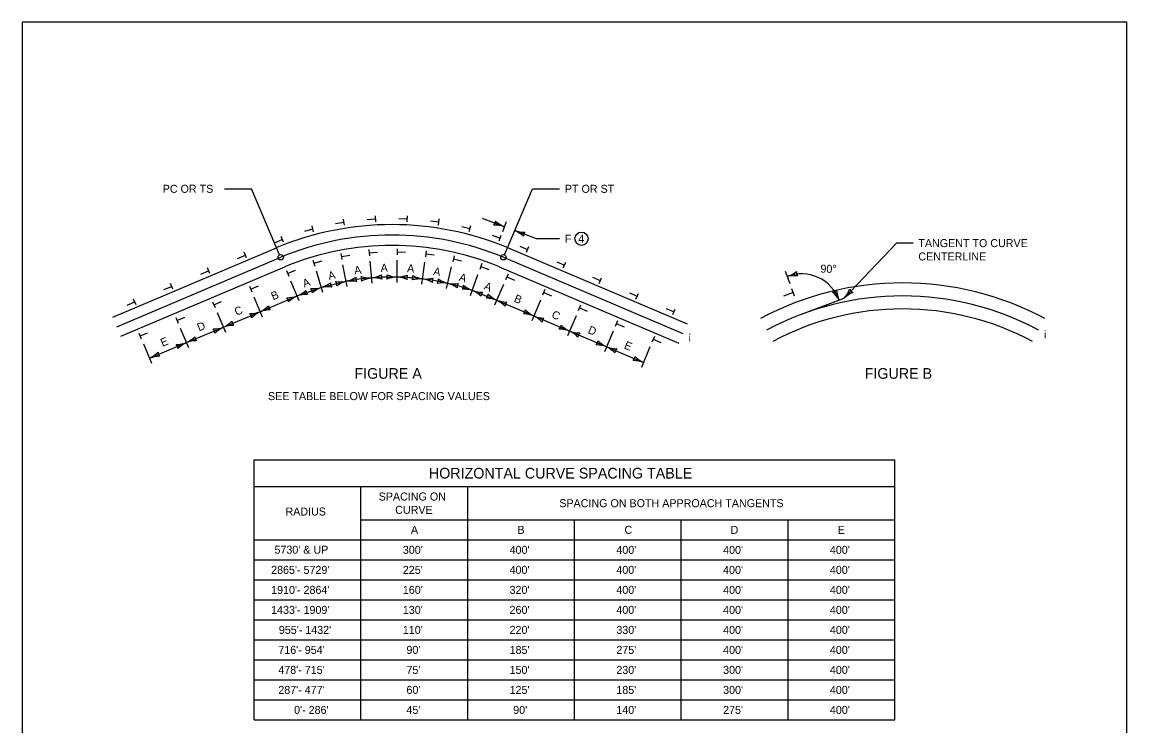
# Model space of a CAD drawing. Extents: x 49991.4 to 50021, y 49987.6 to 50011.4.
# Drawn here: x 50000.34 to 50008.61, y 50005.99 to 50011.26 of the extents above; entities that cross this region are included whole.
import ezdxf

# ---------------------------------------------------------------- set-up
doc = ezdxf.new("R2010")
doc.units = 0
for name, color, linetype in [('Level 1', 7, 'Continuous'), ('Level 2', 7, 'Continuous'), ('Level 3', 7, 'Continuous'), ('Level 5', 7, 'Continuous')]:
    doc.layers.add(name, color=color, linetype=linetype)

msp = doc.modelspace()

# ---------------------------------------------------------------- linework, layer by layer
at = {"layer": 'Level 1'}
for p, q in [((50002.9853, 50009.7645), (50002.983, 50009.8105)), ((50003.2208, 50009.765), (50003.2233, 50009.811)), ((50002.5205, 50009.6907), (50002.5088, 50009.7352)), ((50002.6849, 50009.7517), (50002.7473, 50009.7626)), ((50002.7509, 50009.7397), (50002.7438, 50009.7852)), ((50002.9209, 50009.7832), (50002.9841, 50009.7875)), ((50003.1587, 50009.7903), (50003.222, 50009.788)), ((50003.3957, 50009.7726), (50003.4585, 50009.7638)), ((50003.455, 50009.7412), (50003.4621, 50009.7866)), ((50003.6302, 50009.7306), (50003.6918, 50009.7156)), ((50003.6858, 50009.6932), (50003.6977, 50009.7377)), ((50002.2943, 50009.6118), (50002.2764, 50009.6542)), ((50002.4536, 50009.6957), (50002.5147, 50009.713)), ((50003.8588, 50009.6645), (50003.9184, 50009.643)), ((50003.9102, 50009.6216), (50003.9267, 50009.6645)), ((50001.0157, 50009.0503), (50002.243, 50009.5712)), ((50002.9344, 50009.5567), (50002.9382, 50009.5108)), ((50003.1466, 50009.5635), (50003.1457, 50009.5175)), ((50003.3634, 50009.548), (50003.3576, 50009.5023)), ((50003.9719, 50009.5714), (50005.3185, 50008.9999)), ((50004.115, 50009.5367), (50004.1329, 50009.579)), ((50002.0181, 50009.4946), (50002.0001, 50009.5369)), ((50002.5154, 50009.4773), (50002.5289, 50009.4334)), ((50002.7237, 50009.528), (50002.7324, 50009.4828)), ((50003.5731, 50009.5109), (50003.5626, 50009.4661)), ((50001.0767, 50008.9065), (50002.304, 50009.4274)), ((50001.7419, 50009.3773), (50001.7239, 50009.4197)), ((50002.3157, 50009.3993), (50002.3337, 50009.3569)), ((50003.7798, 50009.4517), (50003.7646, 50009.4083)), ((50003.9114, 50009.4274), (50005.2575, 50008.8561)), ((50004.3912, 50009.4194), (50004.4092, 50009.4618)), ((50001.4656, 50009.2601), (50001.4476, 50009.3024)), ((50003.9769, 50009.3737), (50003.9589, 50009.3313)), ((50004.6593, 50009.3035), (50004.6772, 50009.3458)), ((50006.9294, 50009.307), (50006.9294, 50009.307)), ((50002.0394, 50009.282), (50002.0574, 50009.2397)), ((50004.2531, 50009.2564), (50004.2352, 50009.2141)), ((50004.9355, 50009.1862), (50004.9535, 50009.2286)), ((50006.1148, 50009.2345), (50006.0406, 50009.2067)), ((50006.1248, 50009.2079), (50006.1046, 50009.2619)), ((50001.1893, 50009.1429), (50001.1713, 50009.1852)), ((50001.7632, 50009.1648), (50001.7812, 50009.1224)), ((50004.5212, 50009.1405), (50004.5032, 50009.0981)), ((50006.0497, 50009.1824), (50006.0497, 50009.1824)), ((50006.0497, 50009.1824), (50006.0497, 50009.1824)), ((50005.2118, 50009.069), (50005.2297, 50009.1113)), ((50001.487, 50009.0475), (50001.5049, 50009.0052)), ((50004.7974, 50009.0232), (50004.7795, 50008.9809)), ((50001.2107, 50008.9303), (50001.2286, 50008.888)), ((50005.0737, 50008.906), (50005.0557, 50008.8636))]:
    msp.add_line(p, q, dxfattribs=at)
msp.add_lwpolyline([(50008.6146, 50011.2628), (50000.3356, 50011.2628), (50000.3356, 50000.0624), (50008.6146, 50000.0624)], close=True, dxfattribs=at)
for points in [[(50002.2271, 50009.6083), (50002.2855, 50009.6331)], [(50004.0657, 50009.5826), (50004.1241, 50009.5578)], [(50001.9508, 50009.4911), (50002.0092, 50009.5159)], [(50002.5224, 50009.4553), (50002.5834, 50009.4725)], [(50002.7283, 50009.5053), (50002.7908, 50009.5163)], [(50002.9365, 50009.5336), (50002.9998, 50009.5382)], [(50003.1464, 50009.5405), (50003.2098, 50009.5384)], [(50003.3607, 50009.5251), (50003.4235, 50009.5164)], [(50003.568, 50009.4884), (50003.6293, 50009.4734)], [(50004.342, 50009.4653), (50004.4004, 50009.4405)], [(50001.6745, 50009.3738), (50001.7329, 50009.3986)], [(50002.3249, 50009.3781), (50002.3833, 50009.4029)], [(50003.7724, 50009.43), (50003.8321, 50009.4085)], [(50003.9679, 50009.3524), (50004.0263, 50009.3276)], [(50004.61, 50009.3494), (50004.6684, 50009.3246)], [(50001.3982, 50009.2565), (50001.4566, 50009.2813)], [(50002.0486, 50009.2609), (50002.107, 50009.2857)], [(50004.2442, 50009.2351), (50004.3026, 50009.2103)], [(50004.8863, 50009.2321), (50004.9447, 50009.2073)], [(50001.1219, 50009.1393), (50001.1803, 50009.1641)], [(50001.7723, 50009.1436), (50001.8307, 50009.1684)], [(50004.5122, 50009.1192), (50004.5706, 50009.0944)], [(50005.1626, 50009.1149), (50005.221, 50009.0901)], [(50001.496, 50009.0263), (50001.5544, 50009.0511)], [(50004.7885, 50009.0019), (50004.8469, 50008.9771)], [(50001.2197, 50008.9091), (50001.2781, 50008.9339)], [(50005.0648, 50008.8847), (50005.1232, 50008.8599)]]:
    msp.add_lwpolyline(points, dxfattribs=at)
for centre in [(50002.2735, 50009.4993), (50003.9419, 50009.4993)]:
    msp.add_circle(centre, 0.02, dxfattribs=at)
for centre, radius, start, end in [((50003.1077, 50007.4941), 2.2499, 67.41183, 112.58817), ((50003.1077, 50007.4941), 2.0937, 67.41183, 112.58817), ((50006.934, 50007.0492), 2.2578, 61.85387, 118.14614), ((50006.934, 50007.0492), 2.0625, 61.85387, 118.14614)]:
    msp.add_arc(centre, radius, start, end, dxfattribs=at)
at = {"layer": 'Level 2'}
for p, q in [((50002.0751, 50007.9803), (50006.8751, 50007.9803)), ((50002.0751, 50006.0303), (50002.0751, 50007.9803)), ((50006.8751, 50006.0303), (50006.8751, 50007.9803)), ((50002.0751, 50007.7803), (50006.8751, 50007.7803)), ((50002.8751, 50006.0303), (50002.8751, 50007.7803)), ((50003.6751, 50006.0303), (50003.6751, 50007.7803)), ((50002.8751, 50007.5303), (50006.8751, 50007.5303)), ((50004.4751, 50006.0303), (50004.4751, 50007.5303)), ((50005.2751, 50006.0303), (50005.2751, 50007.5303)), ((50006.0751, 50006.0303), (50006.0751, 50007.5303)), ((50002.0751, 50007.3803), (50006.8751, 50007.3803)), ((50002.0751, 50007.2303), (50006.8751, 50007.2303)), ((50002.0751, 50007.0803), (50006.8751, 50007.0803)), ((50002.0751, 50006.9303), (50006.8751, 50006.9303)), ((50002.0751, 50006.7803), (50006.8751, 50006.7803)), ((50002.0751, 50006.6303), (50006.8751, 50006.6303)), ((50002.0751, 50006.4803), (50006.8751, 50006.4803)), ((50002.0751, 50006.3303), (50006.8751, 50006.3303)), ((50002.0751, 50006.1803), (50006.8751, 50006.1803)), ((50002.0751, 50006.0303), (50006.8751, 50006.0303))]:
    msp.add_line(p, q, dxfattribs=at)
msp.add_circle((50004.5276, 50009.6383), 0.05, dxfattribs=at)
at = {"layer": 'Level 3'}
for p, q in [((50001.8522, 50010.0127), (50002.0556, 50010.0127)), ((50002.2657, 50009.5177), (50002.0556, 50010.0127)), ((50003.9497, 50009.5177), (50004.1598, 50010.0127)), ((50004.1598, 50010.0127), (50004.3631, 50010.0127)), ((50003.9488, 50009.7286), (50003.7865, 50009.7896)), ((50003.9629, 50009.7661), (50003.9348, 50009.6912)), ((50004.1891, 50009.6383), (50004.0268, 50009.6993)), ((50004.3631, 50009.6383), (50004.1891, 50009.6383)), ((50006.8868, 50009.6055), (50006.4969, 50009.1923)), ((50006.8843, 50009.6045), (50006.8843, 50009.6045)), ((50007.0118, 50009.6055), (50006.8868, 50009.6055)), ((50002.9578, 50009.3048), (50002.9431, 50009.4711)), ((50003.1453, 50009.3106), (50003.1456, 50009.4775)), ((50002.5893, 50009.2354), (50002.5406, 50009.3951)), ((50002.7718, 50009.2796), (50002.74, 50009.4435)), ((50003.3323, 50009.297), (50003.3527, 50009.4626)), ((50003.5168, 50009.2643), (50003.5537, 50009.4271)), ((50002.412, 50009.1731), (50002.3494, 50009.3201)), ((50002.5776, 50009.2737), (50002.7642, 50009.3189)), ((50003.697, 50009.2127), (50003.7515, 50009.3705)), ((50002.3963, 50009.2099), (50002.5776, 50009.2737)), ((50003.71, 50009.2506), (50003.8916, 50009.1777)), ((50003.9429, 50009.2946), (50003.876, 50009.1409)), ((50002.0727, 50009.2027), (50002.1344, 50009.0539)), ((50002.1188, 50009.0908), (50002.3963, 50009.2099)), ((50003.8916, 50009.1777), (50004.1698, 50009.0595)), ((50004.2196, 50009.1773), (50004.1542, 50009.0227)), ((50001.7968, 50009.0856), (50001.8595, 50008.9374)), ((50001.8439, 50008.9742), (50002.1188, 50009.0908)), ((50002.1176, 50009.0934), (50002.1176, 50009.0934)), ((50002.1185, 50009.0914), (50002.1185, 50009.0914)), ((50004.1698, 50009.0595), (50004.9921, 50008.7106)), ((50004.4874, 50009.0613), (50004.4221, 50008.909)), ((50001.5205, 50008.9684), (50001.5824, 50008.8227)), ((50001.5668, 50008.8595), (50001.8439, 50008.9742)), ((50004.7639, 50008.9441), (50004.6993, 50008.7914)), ((50001.2443, 50008.8512), (50001.3062, 50008.7059)), ((50001.2907, 50008.7428), (50001.5668, 50008.8595)), ((50001.5677, 50008.8599), (50001.5677, 50008.8599)), ((50005.0403, 50008.8267), (50004.9764, 50008.6738))]:
    msp.add_line(p, q, dxfattribs=at)
for points in [[(50006.0906, 50009.2994), (50006.0554, 50009.393)], [(50006.1758, 50009.0719), (50006.4969, 50009.1923)]]:
    msp.add_lwpolyline(points, dxfattribs=at)
for centre, radius, start, end in [((50003.8288, 50009.7737), 0.0548, 321.53681, 357.25917), ((50003.8777, 50009.5068), 0.233, 72.2253, 91.47515), ((50004.0356, 50009.9333), 0.2223, 226.854, 247.03751), ((50003.94, 50009.4946), 0.2223, 46.854, 67.03751), ((50004.0979, 50009.9212), 0.233, 252.2253, 271.47515), ((50004.1468, 50009.6542), 0.0548, 141.53681, 177.25917), ((50005.9964, 50009.5768), 0.233, 288.28852, 307.53837), ((50006.193, 50009.3897), 0.0548, 177.60003, 213.32239), ((50002.5116, 50009.4971), 0.233, 286.45167, 305.70152), ((50002.7022, 50009.3039), 0.0548, 175.76318, 211.48554), ((50002.7207, 50009.537), 0.2223, 261.08998, 281.27349), ((50002.6396, 50009.2887), 0.0548, 355.77279, 31.49515), ((50002.8302, 50009.0955), 0.233, 106.46128, 125.71113), ((50002.7102, 50009.5456), 0.233, 283.37865, 302.6285), ((50003.1077, 50007.4941), 1.8569, 94.7392, 100.66168), ((50002.7958, 50009.0989), 0.2223, 78.00735, 98.19086), ((50002.8902, 50009.3424), 0.0548, 172.69016, 208.41252), ((50002.9442, 50009.5667), 0.2223, 252.42166, 272.60517), ((50002.8266, 50009.3335), 0.0548, 347.10447, 22.82683), ((50002.9859, 50009.1138), 0.233, 97.79296, 117.04281), ((50002.9246, 50009.5757), 0.233, 277.32551, 296.57536), ((50003.1077, 50007.4941), 1.8569, 88.81992, 94.7392), ((50002.9626, 50009.1225), 0.2223, 71.95421, 92.13771), ((50003.0821, 50009.3547), 0.0548, 166.63701, 202.35938), ((50003.0177, 50009.3528), 0.0548, 341.16014, 16.88251), ((50003.1535, 50009.1177), 0.233, 91.84864, 111.09849), ((50003.1589, 50009.5725), 0.2223, 246.47734, 266.66084), ((50003.1396, 50009.5835), 0.233, 271.55569, 290.80554), ((50003.1077, 50007.4941), 1.8569, 82.90288, 88.81992), ((50003.1319, 50009.1287), 0.2223, 66.18439, 86.3679), ((50003.2741, 50009.3477), 0.0548, 160.8672, 196.58956), ((50003.2099, 50009.3521), 0.0548, 335.2574, 10.97976), ((50003.3207, 50009.1043), 0.233, 85.94589, 105.19574), ((50003.3729, 50009.5562), 0.2223, 240.57459, 260.7581), ((50003.1077, 50007.4941), 1.8569, 76.98832, 82.90288), ((50003.3557, 50009.569), 0.233, 265.43388, 284.68373), ((50003.2995, 50009.1176), 0.2223, 60.06258, 80.24609), ((50003.4643, 50009.3202), 0.0548, 154.74539, 190.46775), ((50003.4007, 50009.3317), 0.0548, 329.3481, 5.07046), ((50003.4855, 50009.0738), 0.233, 80.03659, 99.28644), ((50003.5839, 50009.5179), 0.2223, 234.66529, 254.8488), ((50003.1077, 50007.4941), 1.8569, 71.07056, 76.98674), ((50003.4665, 50009.089), 0.2223, 54.36564, 74.54915), ((50003.5673, 50009.5326), 0.233, 259.73694, 278.98679), ((50003.6507, 50009.2743), 0.0548, 149.04845, 184.77081), ((50006.1758, 50009.0719), 0.3029, 20.54783, 110.55074), ((50006.1199, 50009.139), 0.2223, 82.91722, 103.10073), ((50002.3083, 50009.4256), 0.233, 292.21393, 311.46378), ((50002.4614, 50008.9973), 0.2223, 86.84263, 107.02614), ((50002.5173, 50009.2525), 0.0548, 181.52544, 217.2478), ((50002.5125, 50009.4863), 0.2223, 266.83342, 287.01693), ((50002.4566, 50009.2311), 0.0548, 1.51623, 37.23859), ((50002.6657, 50009.058), 0.233, 112.20472, 131.45457), ((50002.621, 50009.0556), 0.2223, 81.08037, 101.26388), ((50003.5886, 50009.2917), 0.0548, 323.43948, 359.16184), ((50003.6463, 50009.0265), 0.233, 74.12797, 93.37782), ((50003.7899, 50009.458), 0.2223, 228.75667, 248.94018), ((50003.6188, 50009.0478), 0.2223, 45.58928, 65.77279), ((50003.786, 50009.4708), 0.233, 250.96058, 270.21043), ((50003.829, 50009.2028), 0.0548, 140.27209, 175.99445), ((50003.7738, 50009.2282), 0.0548, 318.95023, 354.67259), ((50003.9875, 50009.3783), 0.2223, 224.26742, 244.45093), ((50006.3999, 50009.2918), 0.0548, 279.77892, 315.50129), ((50006.2586, 50009.0601), 0.233, 30.46742, 49.71727), ((50006.6605, 50009.2732), 0.2223, 185.09612, 205.27962), ((50006.3197, 50009.3436), 0.233, 319.49291, 338.74276), ((50006.6522, 50009.0332), 0.2223, 114.12161, 134.30512), ((50006.5849, 50009.2855), 0.0548, 208.80442, 244.52678), ((50002.0174, 50009.3005), 0.233, 295.79908, 315.04893), ((50002.2368, 50009.1408), 0.0548, 185.11059, 220.83295), ((50002.3181, 50009.418), 0.2223, 270.42778, 290.61129), ((50002.2783, 50009.1599), 0.0548, 5.11059, 40.83295), ((50002.4977, 50009.0001), 0.233, 115.79908, 135.04893), ((50003.8106, 50008.9592), 0.233, 69.63872, 88.88857), ((50003.7964, 50008.9768), 0.2223, 44.44431, 64.62782), ((50003.972, 50009.3964), 0.233, 249.81561, 269.06546), ((50004.0097, 50009.1276), 0.0548, 139.12712, 174.84948), ((50002.0405, 50009.2989), 0.2223, 270.42278, 290.60629), ((50002.0007, 50009.0407), 0.0548, 5.10559, 40.82795), ((50002.2202, 50008.881), 0.233, 115.79408, 135.04393), ((50002.197, 50008.8827), 0.2223, 90.42778, 110.61129), ((50004.052, 50009.1101), 0.0548, 318.90671, 354.62908), ((50004.0886, 50008.8411), 0.233, 69.59521, 88.84506), ((50004.2659, 50009.26), 0.2223, 224.22391, 244.40741), ((50004.0701, 50008.8608), 0.2223, 43.16719, 63.3507), ((50004.2551, 50009.2763), 0.233, 248.53849, 267.78834), ((50001.7714, 50009.1844), 0.2223, 268.85123, 289.03474), ((50001.9395, 50008.7617), 0.233, 114.22253, 133.47238), ((50001.7425, 50009.184), 0.233, 295.79408, 315.04393), ((50001.9221, 50008.7661), 0.2223, 90.42278, 110.60629), ((50001.9619, 50009.0243), 0.0548, 185.10559, 220.82795), ((50004.2867, 50009.0067), 0.0548, 137.85, 173.57236), ((50004.3197, 50008.996), 0.0548, 319.11559, 354.83795), ((50004.533, 50009.1467), 0.2223, 224.43278, 244.61629), ((50001.4684, 50009.0707), 0.233, 294.9894, 314.23925), ((50001.6856, 50008.9079), 0.0548, 184.30091, 220.02327), ((50001.7245, 50008.9275), 0.0548, 3.53404, 39.2564), ((50004.3573, 50008.7272), 0.233, 69.80408, 89.05393), ((50004.3425, 50008.7449), 0.2223, 44.45884, 64.64235), ((50004.518, 50009.1645), 0.233, 249.83014, 269.07999), ((50004.5557, 50008.8957), 0.0548, 139.14165, 174.86401), ((50001.4887, 50009.0677), 0.2223, 270.37463, 290.55813), ((50001.4487, 50008.8096), 0.0548, 5.05743, 40.77979), ((50001.668, 50008.6497), 0.233, 115.74593, 134.99578), ((50001.6421, 50008.6504), 0.2223, 89.6181, 109.80161), ((50004.5969, 50008.8783), 0.0548, 319.14165, 354.86401), ((50004.6346, 50008.6095), 0.233, 69.83014, 89.07999), ((50004.8102, 50009.0291), 0.2223, 224.45884, 244.64235), ((50004.6196, 50008.6273), 0.2223, 44.43618, 64.61968), ((50004.7954, 50009.0469), 0.233, 249.80748, 269.05732), ((50004.8329, 50008.7781), 0.0548, 139.11898, 174.84134), ((50001.1895, 50008.9527), 0.233, 295.74592, 314.99577), ((50001.3687, 50008.5346), 0.2223, 90.37463, 110.55813), ((50001.4088, 50008.7927), 0.0548, 185.05743, 220.77979), ((50004.874, 50008.7608), 0.0548, 319.11898, 354.84134), ((50004.9116, 50008.4919), 0.233, 69.80747, 89.05732), ((50005.0873, 50008.9115), 0.2223, 224.43618, 244.61968)]:
    msp.add_arc(centre, radius, start, end, dxfattribs=at)
at = {"layer": 'Level 5'}
for p, q in [((50001.0462, 50008.9784), (50002.2735, 50009.4993)), ((50003.942, 50009.4994), (50005.288, 50008.928))]:
    msp.add_line(p, q, dxfattribs=at)
for centre, radius, start, end in [((50003.1079, 50007.4932), 2.1727, 67.4234, 112.58347), ((50006.934, 50007.0492), 2.1601, 61.85387, 118.14584)]:
    msp.add_arc(centre, radius, start, end, dxfattribs=at)

# ---------------------------------------------------------------- texts
at = {"layer": 'Level 2'}
for s, height, p in [('PC OR TS', 0.06, (50001.3894, 50009.9827)), ('PT OR ST', 0.06, (50004.4031, 50009.9827)), ('F', 0.06, (50004.4031, 50009.6083)), ('4', 0.06, (50004.5036, 50009.6083)), ('TANGENT TO CURVE', 0.06, (50007.0518, 50009.5755)), ('CENTERLINE', 0.06, (50007.0518, 50009.4755)), ('¡', 0.06, (50005.3248, 50008.8824)), ('¡', 0.06, (50007.9884, 50008.9052)), ('FIGURE A', 0.08, (50002.8258, 50008.5882)), ('FIGURE B', 0.08, (50006.6495, 50008.5882)), ('SEE TABLE BELOW FOR SPACING VALUES', 0.06, (50002.1784, 50008.4282)), ('HORIZONTAL CURVE SPACING TABLE', 0.08, (50003.3838, 50007.8403)), ('SPACING ON', 0.06, (50003.0077, 50007.6753)), ('SPACING ON BOTH APPROACH TANGENTS', 0.06, (50004.3612, 50007.6253)), ('RADIUS', 0.06, (50002.3093, 50007.5628)), ('CURVE', 0.06, (50003.1315, 50007.5753)), ('A', 0.06, (50003.2494, 50007.4253)), ('B', 0.06, (50004.0474, 50007.4253)), ('C', 0.06, (50004.8495, 50007.4253)), ('D', 0.06, (50005.6448, 50007.4253)), ('E', 0.06, (50006.4471, 50007.4253)), ("5730' & UP", 0.06, (50002.2268, 50007.2766)), ("300'", 0.06, (50003.1888, 50007.2753)), ("400'", 0.06, (50003.9888, 50007.2753)), ("400'", 0.06, (50004.7888, 50007.2753)), ("400'", 0.06, (50005.5888, 50007.2753)), ("400'", 0.06, (50006.3888, 50007.2753)), ("2865'- 5729'", 0.06, (50002.2018, 50007.1253)), ("225'", 0.06, (50003.1887, 50007.1253)), ("400'", 0.06, (50003.9887, 50007.1253)), ("400'", 0.06, (50004.7888, 50007.1253)), ("400'", 0.06, (50005.5887, 50007.1253)), ("400'", 0.06, (50006.3888, 50007.1253)), ("1910'- 2864'", 0.06, (50002.2018, 50006.9753)), ("160'", 0.06, (50003.1888, 50006.9753)), ("320'", 0.06, (50003.9887, 50006.9753)), ("400'", 0.06, (50004.7887, 50006.9753)), ("400'", 0.06, (50005.5888, 50006.9753)), ("400'", 0.06, (50006.3888, 50006.9753)), ("1433'- 1909'", 0.06, (50002.2018, 50006.8253)), ("130'", 0.06, (50003.1887, 50006.8253)), ("260'", 0.06, (50003.9887, 50006.8253)), ("400'", 0.06, (50004.7888, 50006.8253)), ("400'", 0.06, (50005.5888, 50006.8253)), ("400'", 0.06, (50006.3888, 50006.8253)), ("955'- 1432'", 0.06, (50002.2596, 50006.6753)), ("110'", 0.06, (50003.1887, 50006.6753)), ("220'", 0.06, (50003.9887, 50006.6753)), ("330'", 0.06, (50004.7888, 50006.6753)), ("400'", 0.06, (50005.5888, 50006.6753)), ("400'", 0.06, (50006.3888, 50006.6753)), ("716'- 954'", 0.06, (50002.2557, 50006.5253)), ("90'", 0.06, (50003.2157, 50006.5253)), ("185'", 0.06, (50003.9887, 50006.5253)), ("275'", 0.06, (50004.7888, 50006.5253)), ("400'", 0.06, (50005.5888, 50006.5253)), ("400'", 0.06, (50006.3888, 50006.5253)), ("478'- 715'", 0.06, (50002.2557, 50006.3753)), ("75'", 0.06, (50003.2158, 50006.3753)), ("150'", 0.06, (50003.9887, 50006.3753)), ("230'", 0.06, (50004.7887, 50006.3753)), ("300'", 0.06, (50005.5888, 50006.3753)), ("400'", 0.06, (50006.3888, 50006.3753)), ("287'- 477'", 0.06, (50002.2557, 50006.2253)), ("60'", 0.06, (50003.2157, 50006.2253)), ("125'", 0.06, (50003.9887, 50006.2253)), ("185'", 0.06, (50004.7887, 50006.2253)), ("300'", 0.06, (50005.5888, 50006.2253)), ("400'", 0.06, (50006.3888, 50006.2253)), ("0'- 286'", 0.06, (50002.374, 50006.0753)), ("45'", 0.06, (50003.2157, 50006.0753)), ("90'", 0.06, (50004.0157, 50006.0753)), ("140'", 0.06, (50004.7887, 50006.0753)), ("275'", 0.06, (50005.5888, 50006.0753)), ("400'", 0.06, (50006.3888, 50006.0753))]:
    msp.add_text(s, height=height, dxfattribs=at).set_placement(p)
for s, rotation, p in [('A', 13.62436, (50002.6363, 50009.3291)), ('A', 7.70025, (50002.828, 50009.3704)), ('A', 1.78663, (50003.0231, 50009.3893)), ('A', 1.77305, (50003.0231, 50009.3893)), ('A', 355.86163, (50003.2191, 50009.3878)), ('A', 349.98721, (50003.4135, 50009.3663)), ('90°', 359.02821, (50006.3177, 50009.3841)), ('A', 19.38662, (50002.4499, 50009.2712)), ('A', 344.02963, (50003.6049, 50009.3249)), ('A', 338.13327, (50003.7919, 50009.2608)), ('B', 22.97443, (50002.2162, 50009.1763)), ('B', 336.97957, (50004.0161, 50009.1683)), ('C', 22.97426, (50001.9424, 50009.0594)), ('C', 337.0086, (50004.2979, 50009.0486)), ('D', 22.48613, (50001.6621, 50008.9423)), ('D', 337.0086, (50004.5706, 50008.9329)), ('E', 22.91861, (50001.3881, 50008.8274)), ('E', 337.0086, (50004.8414, 50008.818))]:
    msp.add_text(s, height=0.06, rotation=rotation, dxfattribs=at).set_placement(p)

doc.saveas('drawing.dxf')
